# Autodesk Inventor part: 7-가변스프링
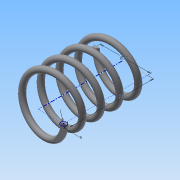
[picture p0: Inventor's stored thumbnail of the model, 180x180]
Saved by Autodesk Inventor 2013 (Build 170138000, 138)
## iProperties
Created: 2015-03
Part Number: 7-가변스프링
Material: 강철, 탄소
Document SubType Name: Modeling
Designer: Administrator
Density: 7.87 g/cm^3
Mass: 48.2733 g
Surface Area: 62.0009 cm^2
Volume: 6.13383 cm^3
Author: Administrator
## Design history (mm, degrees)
sketch "스케치1"
  geometry: L1 (0, 0)-(17.5, 0); L2 (17.5, 0)-(17.5, 43.5); L3 (17.5, 43.5)-(0, 43.5); L4 (0, 43.5)-(0, 0); C1 r 2 at (17.5, 0)
  constraints: 8 end point, 2 parallel, 1 centre point, 1 coincident, 1 horizontal, 1 perpendicular
  dimensions: "d0" = 4 diameter of C1; "d2" = 35 diameter of L2 L4; "d3" = 43.5 distance of L1.end L2.end (derived)
feature "코일1" pitch "d4" = 10; turns "d6" = 4.5; dims "d5" = 43.5 (= d3), "d7" = 0, angle "d8" = 90 deg, angle "d9" = 90 deg, "d10" = 0, "d11" = 0
sketch "스케치2"
  geometry: L1 (-19.5, 0)-(-15.5, 0) reference; 1 further point
  constraints: 1 horizontal alignment
extrude "돌출1" cut sketch "스케치2" stored distance "d12" = 10; taper "d13" = 0 deg
node "작업 평면1"
sketch "스케치3"
  geometry: L1 (-19.5, 0)-(-15.5, 0) reference; 1 further point
  constraints: 1 horizontal alignment
extrude "돌출2" cut sketch "스케치3" stored distance "d15" = 10; taper "d16" = 0 deg
node "솔리드1"
node "절단 모서리 투영1"
node "절단 모서리 투영2"
other parameters: "d14" = -43.5 (= -d3)
